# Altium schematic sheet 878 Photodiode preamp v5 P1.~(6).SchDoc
size A4
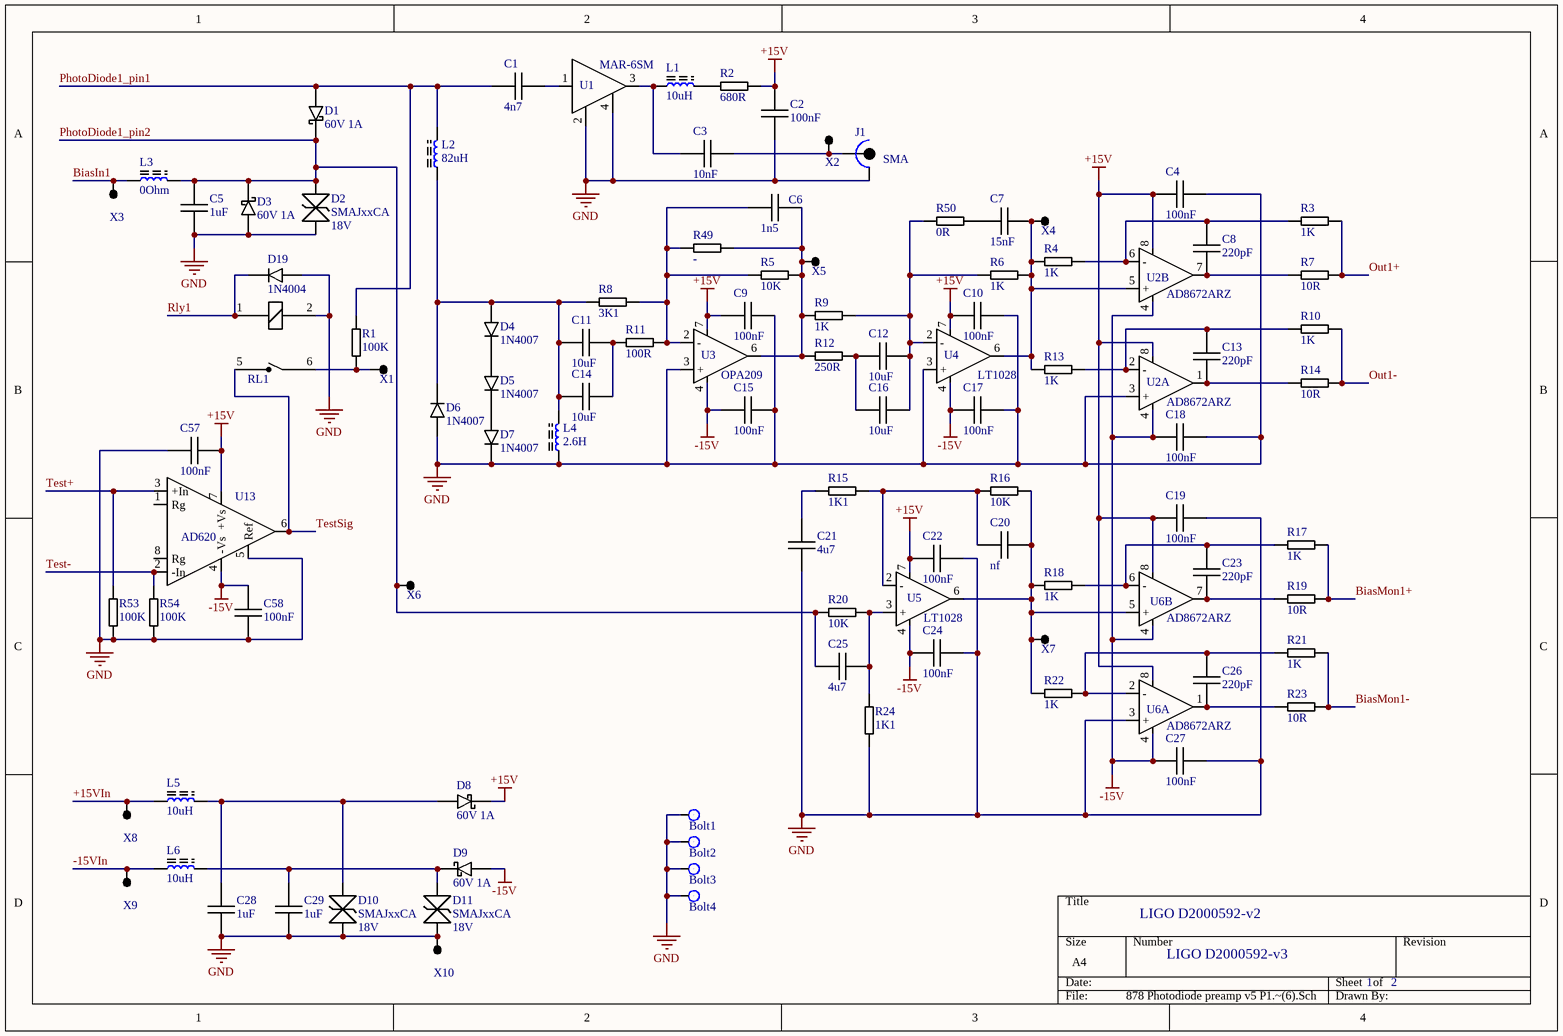
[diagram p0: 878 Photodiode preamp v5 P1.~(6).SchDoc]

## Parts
Bolt1  Bolt M3  [BOLT]  (value not drawn)
Bolt2  Bolt M3  [BOLT]  (value not drawn)
Bolt3  Bolt M3  [BOLT]  (value not drawn)
Bolt4  Bolt M3  [BOLT]  (value not drawn)
C1  value 4n7  [HS0805Long]  (hidden comment: Cap200)
C2  value 100nF  [HS0805Long]  (hidden comment: Cap200)
C3  value 10nF  [HS0805Long]  (hidden comment: Cap200)
C4  value 100nF  [HS0805Long]  (hidden comment: Cap200)
C5  value 1uF  [HS0805Long]  (hidden comment: Cap200)
C6  value 1n5  [HS0805Long]  (hidden comment: Cap200)
C7  value 15nF  [HS0805Long]  (hidden comment: Cap200)
C8  value 220pF  [HS0805Long]  (hidden comment: Cap200)
C9  value 100nF  [HS0805Long]  (hidden comment: Cap200)
C10  value 100nF  [HS0805Long]  (hidden comment: Cap200)
C11  value 10uF  [MKS2 7.2 11]  (hidden comment: Cap200)
C12  value 10uF  [MKS2 7.2 11]  (hidden comment: Cap200)
C13  value 220pF  [HS0805Long]  (hidden comment: Cap200)
C14  value 10uF  [MKS2 7.2 11]  (hidden comment: Cap200)
C15  value 100nF  [HS0805Long]  (hidden comment: Cap200)
C16  value 10uF  [MKS2 7.2 11]  (hidden comment: Cap200)
C17  value 100nF  [HS0805Long]  (hidden comment: Cap200)
C18  value 100nF  [HS0805Long]  (hidden comment: Cap200)
C19  value 100nF  [HS0805Long]  (hidden comment: Cap200)
C20  value nf  [HS0805Long]  (hidden comment: Cap200)
C21  value 4u7  [MKS2 7.2 8.5]  (hidden comment: Cap200)
C22  value 100nF  [HS0805Long]  (hidden comment: Cap200)
C23  value 220pF  [HS0805Long]  (hidden comment: Cap200)
C24  value 100nF  [HS0805Long]  (hidden comment: Cap200)
C25  value 4u7  [MKS2 7.2 8.5]  (hidden comment: Cap200)
C26  value 220pF  [HS0805Long]  (hidden comment: Cap200)
C27  value 100nF  [HS0805Long]  (hidden comment: Cap200)
C28  value 1uF  [HS0805Long]  (hidden comment: Cap200)
C29  value 1uF  [HS0805Long]  (hidden comment: Cap200)
C57  value 100nF  [HS0805Long]  (hidden comment: Cap200)
C58  value 100nF  [HS0805Long]  (hidden comment: Cap200)
D1  60V 1A  [SOD123]
D2  SMAJxxCA  [DO214AC]
D3  60V 1A  [SOD123]
D4  1N4007  [DO214AC]
D5  1N4007  [DO214AC]
D6  1N4007  [DO214AC]
D7  1N4007  [DO214AC]
D8  60V 1A  [SOD123]
D9  60V 1A  [SOD123]
D10  SMAJxxCA  [DO214AC]
D11  SMAJxxCA  [DO214AC]
D19  1N4004  [DO214AC]
J1  SMA  [PCB SMB]
L1  value 10uH  [HS1210]  (hidden comment: Inductor)
L2  value 82uH  [HS1210]  (hidden comment: Inductor)
L3  value 0Ohm  [HS1210]  (hidden comment: Inductor)
L4  value 2.6H  [2 way 0.1"]  (hidden comment: Inductor)
L5  value 10uH  [HS1210]  (hidden comment: Inductor)
L6  value 10uH  [HS1210]  (hidden comment: Inductor)
R1  value 100K  [hs0805long]  (hidden comment: Res)
R2  value 680R  [hs0805long]  (hidden comment: Res)
R3  value 1K  [hs0805long]  (hidden comment: Res)
R4  value 1K  [hs0805long]  (hidden comment: Res)
R5  value 10K  [SpecialR]  (hidden comment: Res)
R6  value 1K  [hs0805long]  (hidden comment: Res)
R7  value 10R  [hs0805long]  (hidden comment: Res)
R8  value 3K1  [hs0805long]  (hidden comment: Res)
R9  value 1K  [hs0805long]  (hidden comment: Res)
R10  value 1K  [hs0805long]  (hidden comment: Res)
R11  value 100R  [hs0805long]  (hidden comment: Res)
R12  value 250R  [hs0805long]  (hidden comment: Res)
R13  value 1K  [hs0805long]  (hidden comment: Res)
R14  value 10R  [hs0805long]  (hidden comment: Res)
R15  value 1K1  [hs0805long]  (hidden comment: Res)
R16  value 10K  [hs0805long]  (hidden comment: Res)
R17  value 1K  [hs0805long]  (hidden comment: Res)
R18  value 1K  [hs0805long]  (hidden comment: Res)
R19  value 10R  [hs0805long]  (hidden comment: Res)
R20  value 10K  [hs0805long]  (hidden comment: Res)
R21  value 1K  [hs0805long]  (hidden comment: Res)
R22  value 1K  [hs0805long]  (hidden comment: Res)
R23  value 10R  [hs0805long]  (hidden comment: Res)
R24  value 1K1  [hs0805long]  (hidden comment: Res)
R49  Res  [hs0805long]  (value not drawn)
R50  value 0R  [hs0805long]  (hidden comment: Res)
R53  value 100K  [hs0805long]  (hidden comment: Res)
R54  value 100K  [hs0805long]  (hidden comment: Res)
RL1  9901 relay  [9901 Relay]  (value not drawn)
U1  MAR-6SM  [ww107]
U2  AD8672ARZ  [SOIC 8]  (parts A,B of 2)
U3  OPA209  [SOIC 8]
U4  LT1028  [SOIC 8]
U5  LT1028  [SOIC 8]
U6  AD8672ARZ  [SOIC 8]  (parts A,B of 2)
U13  AD620  [SOIC 8]
X1  TestPoint  [SM Test point]  (value not drawn)
X2  TestPoint  [SM Test point]  (value not drawn)
X3  TestPoint  [SM Test point]  (value not drawn)
X4  TestPoint  [SM Test point]  (value not drawn)
X5  TestPoint  [SM Test point]  (value not drawn)
X6  TestPoint  [SM Test point]  (value not drawn)
X7  TestPoint  [SM Test point]  (value not drawn)
X8  TestPoint  [SM Test point]  (value not drawn)
X9  TestPoint  [SM Test point]  (value not drawn)
X10  TestPoint  [SM Test point]  (value not drawn)

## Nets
+15V: C2.1 C4.1 C9.1 C10.1 C19.1 C22.1 C57.2 D8.K R2.2 U2.8(V+) U3.7(V+) U4.7(V+) U5.7(V+) U6.8(V+) U13.7(+Vs)
-15V: C15.1 C17.1 C18.1 C24.1 C27.1 C58.1 D9.A U2.4(V-) U3.4(V-) U4.4(V-) U5.4(V-) U6.4(V-) U13.4(-Vs)
GND: Bolt1.1 Bolt2.1 Bolt3.1 Bolt4.1 C2.2 C4.2 C5.2 C9.2 C10.2 C15.2 C17.2 C18.2 C19.2 C21.1 C22.2 C24.2 C27.2 C28.2 C29.2 C57.1 C58.2 D2.2 D3.A D6.A D7.K D10.1 D11.1 D19.A J1.2(Gnd) L4.1 R24.1 R53.1 R54.1 RL1.2(Coil-) U1.2(gnd1) U1.4(GND2) U2.3(+) U3.3(+) U4.3(+) U6.3(+) U13.5(Ref) X10.1
+15VIn: L5.1 X8.1
-15VIn: L6.1 X9.1
BiasIn1: L3.1 X3.1
BiasMon1+: R17.2 R19.2
BiasMon1-: R21.2 R23.2
Out1+: R3.2 R7.2
Out1-: R10.2 R14.2
PhotoDiode1_pin1: C1.1 D1.A L2.2 R1.2
PhotoDiode1_pin2: C5.1 C25.1 D1.K D2.1 D3.K L3.2 R20.2 X6.1
Rly1: D19.K RL1.1(Coil+)
Test+: R53.2 U13.3(+In)
Test-: R54.2 U13.2(-In)
TestSig: RL1.5(NO) U13.6(Out)
NetC1_2: C1.2 U1.1(IN)
NetC3_1: C3.1 L1.1 U1.3(OUT)
NetC3_2: C3.2 J1.1(Sig) X2.1
NetC6_1: C6.1 R5.1 R8.2 R11.2 R49.1 U3.2(-)
NetC6_2: C6.2 R5.2 R9.1 R12.1 R49.2 U3.6(OP) X5.1
NetC7_1: C7.1 R50.2
NetC7_2: C7.2 R4.1 R6.2 R13.1 U2.5(+) U4.6(OP) X4.1
NetC8_1: C8.1 R3.1 R4.2 U2.6(-)
NetC8_2: C8.2 R7.1 U2.7(OP)
NetC11_1: C11.1 C14.1 D4.A D6.K L2.1 L4.2 R8.1
NetC11_2: C11.2 C14.2 R11.1
NetC12_1: C12.1 C16.1 R12.2
NetC12_2: C12.2 C16.2 R6.1 R9.2 R50.1 U4.2(-)
NetC13_1: C13.1 R10.1 R13.2 U2.2(-)
NetC13_2: C13.2 R14.1 U2.1(OP)
NetC20_1: C20.1 R15.1 R16.1 U5.2(-)
NetC20_2: C20.2 R16.2 R18.1 R22.1 U5.6(OP) U6.5(+) X7.1
NetC21_2: C21.2 R15.2
NetC23_1: C23.1 R17.1 R18.2 U6.6(-)
NetC23_2: C23.2 R19.1 U6.7(OP)
NetC25_2: C25.2 R20.1 R24.2 U5.3(+)
NetC26_1: C26.1 R21.1 R22.2 U6.2(-)
NetC26_2: C26.2 R23.1 U6.1(OP)
NetC28_1: C28.1 D8.A D10.2 L5.2
NetC29_1: C29.1 D9.K D11.2 L6.2
NetD4_K: D4.K D5.A
NetD5_K: D5.K D7.A
NetL1_2: L1.2 R2.1
NetR1_1: R1.1 RL1.6(C) X1.1

Not connected (* = marked no-connect by the designer): U13 1(Rg) 8(Rg)

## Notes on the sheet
- LIGO D2000592-v2
- LIGO D2000592-v3
- 1
- 2

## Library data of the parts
C1-C29 C57 C58 = Cap200: Cap 0.2" pitch
D1 D3 D8 D9 = Sckottky Diode: pin to pad: A>2 K>1
D2 D10 D11 = SMAJxxCA: TVS
D4-D7 D19 = 1N4004: pin to pad: A>2 K>1
J1 = PCB SMB
U2 U6 = DualOpAmp
U3-U5 = SingleOpAmp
